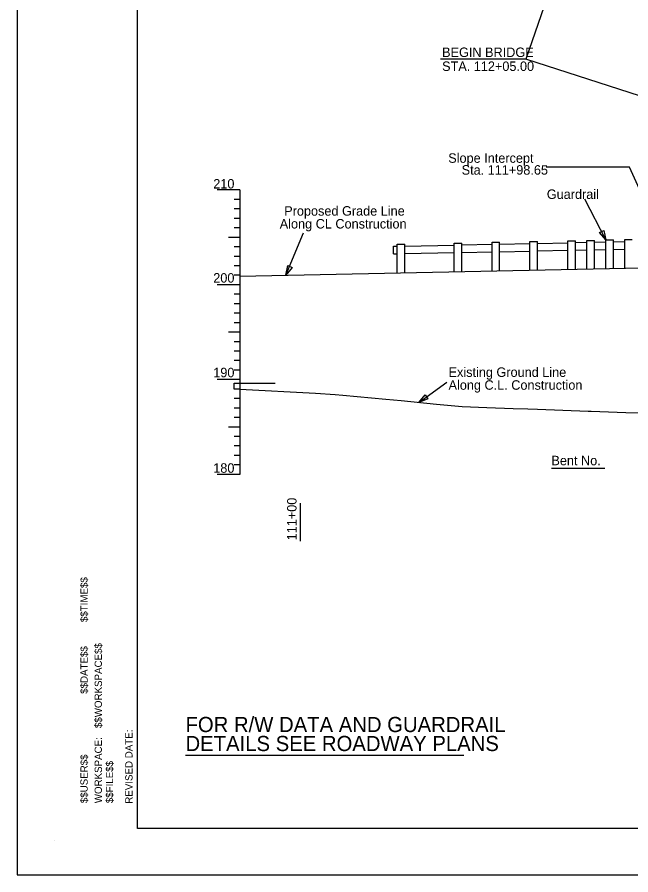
# Model space of a CAD drawing. Extents: x 1385284 to 1385995, y 1975154 to 1975620.
# Drawn here: x 1385283.8 to 1385445.7, y 1975153.7 to 1975379.9 of the extents above; entities that cross this region are included whole.
import ezdxf

# ---------------------------------------------------------------- set-up
doc = ezdxf.new("R2010")
doc.units = 0
for name, color, linetype in [('1', 7, 'Continuous'), ('Default', 7, 'Continuous'), ('Level 1', 7, 'Continuous'), ('R_Axis_Annotation', 7, 'Continuous'), ('R_Exist Surface', 7, 'Continuous'), ('R_Grid Annot', 7, 'Continuous'), ('R_Vert Alg', 7, 'Continuous')]:
    doc.layers.add(name, color=color, linetype=linetype)

msp = doc.modelspace()

# ---------------------------------------------------------------- linework, layer by layer
at = {"layer": '1'}
msp.add_line((1385293.63, 1975162.8), (1385293.63, 1975162.8), dxfattribs=at)
for points in [[(1385994.75, 1975619.62), (1385283.84, 1975619.62), (1385283.84, 1975153.74), (1385994.75, 1975153.74)], [(1385315.54, 1975165.95), (1385315.54, 1975607.41), (1385810.69, 1975607.41), (1385810.69, 1975586.48), (1385892.57, 1975586.48), (1385892.57, 1975580.3), (1385982.69, 1975580.3), (1385982.69, 1975165.95)]]:
    msp.add_lwpolyline(points, close=True, dxfattribs=at)
at = {"layer": 'Default'}
for p, q in [((1385459.1, 1975487.36), (1385417.98, 1975368.8)), ((1385417.98, 1975368.8), (1385395.52, 1975368.8)), ((1385459.1, 1975355.48), (1385417.98, 1975368.8)), ((1385445.3, 1975340.33), (1385423.35, 1975340.33)), ((1385457.22, 1975313.97), (1385445.3, 1975340.33)), ((1385342.56, 1975334.31), (1385342.56, 1975259.31)), ((1385342.56, 1975331.81), (1385341.06, 1975331.81)), ((1385439.08, 1975321.13), (1385433.59, 1975331.88)), ((1385342.56, 1975329.31), (1385341.06, 1975329.31)), ((1385342.56, 1975326.81), (1385341.06, 1975326.81)), ((1385342.56, 1975324.31), (1385341.06, 1975324.31)), ((1385342.56, 1975321.81), (1385339.56, 1975321.81)), ((1385354.71, 1975311.88), (1385359.35, 1975323.02)), ((1385342.56, 1975319.31), (1385341.06, 1975319.31)), ((1385383.07, 1975319.46), (1385384.07, 1975319.48)), ((1385383.07, 1975317.46), (1385383.07, 1975319.46)), ((1385384.07, 1975312.48), (1385384.07, 1975320)), ((1385384.07, 1975320), (1385386.07, 1975320)), ((1385386.07, 1975312.52), (1385386.07, 1975320)), ((1385386.07, 1975319.52), (1385399.07, 1975319.79)), ((1385399.07, 1975312.79), (1385399.07, 1975320.31)), ((1385399.07, 1975320.31), (1385401.07, 1975320.31)), ((1385401.07, 1975312.83), (1385401.07, 1975320.31)), ((1385401.07, 1975319.83), (1385409.07, 1975319.99)), ((1385409.07, 1975312.99), (1385409.07, 1975320.52)), ((1385409.07, 1975320.52), (1385411.07, 1975320.52)), ((1385411.07, 1975313.03), (1385411.07, 1975320.52)), ((1385411.07, 1975320.04), (1385419.07, 1975320.2)), ((1385419.07, 1975313.2), (1385419.07, 1975320.72)), ((1385419.07, 1975320.72), (1385421.07, 1975320.72)), ((1385421.07, 1975313.24), (1385421.07, 1975320.72)), ((1385421.07, 1975320.24), (1385429.07, 1975320.41)), ((1385429.07, 1975313.4), (1385429.07, 1975320.93)), ((1385429.07, 1975320.93), (1385431.07, 1975320.93)), ((1385431.07, 1975313.44), (1385431.07, 1975320.93)), ((1385431.07, 1975320.45), (1385434.07, 1975320.51)), ((1385434.07, 1975313.51), (1385434.07, 1975321.03)), ((1385434.07, 1975321.03), (1385436.07, 1975321.03)), ((1385436.07, 1975313.55), (1385436.07, 1975321.03)), ((1385436.07, 1975320.55), (1385439.07, 1975320.61)), ((1385439.07, 1975313.61), (1385439.07, 1975321.13)), ((1385439.07, 1975321.13), (1385441.07, 1975321.13)), ((1385441.07, 1975313.65), (1385441.07, 1975321.13)), ((1385441.07, 1975320.65), (1385444.07, 1975320.71)), ((1385444.07, 1975313.71), (1385444.07, 1975321.23)), ((1385444.07, 1975321.23), (1385446.07, 1975321.23)), ((1385383.07, 1975317.46), (1385384.07, 1975317.48)), ((1385386.07, 1975317.52), (1385399.07, 1975317.79)), ((1385401.07, 1975317.83), (1385409.07, 1975317.99)), ((1385411.07, 1975318.04), (1385419.07, 1975318.2)), ((1385421.07, 1975318.24), (1385429.07, 1975318.4)), ((1385431.07, 1975318.45), (1385434.07, 1975318.51)), ((1385436.07, 1975318.55), (1385439.07, 1975318.61)), ((1385441.07, 1975318.65), (1385444.07, 1975318.71)), ((1385342.56, 1975316.81), (1385341.06, 1975316.81)), ((1385342.56, 1975314.31), (1385341.06, 1975314.31)), ((1385342.56, 1975311.81), (1385341.06, 1975311.81)), ((1385342.56, 1975306.81), (1385341.06, 1975306.81)), ((1385342.56, 1975304.31), (1385341.06, 1975304.31)), ((1385342.56, 1975301.81), (1385341.06, 1975301.81)), ((1385342.56, 1975299.31), (1385341.06, 1975299.31)), ((1385342.56, 1975296.81), (1385339.56, 1975296.81)), ((1385342.56, 1975294.31), (1385341.06, 1975294.31)), ((1385342.56, 1975291.81), (1385341.06, 1975291.81)), ((1385342.56, 1975289.31), (1385341.06, 1975289.31)), ((1385342.56, 1975286.81), (1385341.06, 1975286.81)), ((1385341.06, 1975281.81), (1385341.06, 1975283.41)), ((1385341.06, 1975283.41), (1385351.89, 1975283.41)), ((1385389.74, 1975278.32), (1385397.15, 1975283.65)), ((1385342.56, 1975281.81), (1385341.06, 1975281.81)), ((1385342.56, 1975279.31), (1385341.06, 1975279.31)), ((1385342.56, 1975276.81), (1385341.06, 1975276.81)), ((1385342.56, 1975274.31), (1385341.06, 1975274.31)), ((1385342.56, 1975271.81), (1385339.56, 1975271.81)), ((1385342.56, 1975269.31), (1385341.06, 1975269.31)), ((1385342.56, 1975266.81), (1385341.06, 1975266.81)), ((1385342.56, 1975264.31), (1385341.06, 1975264.31)), ((1385342.56, 1975261.81), (1385341.06, 1975261.81)), ((1385438.84, 1975260.9), (1385424.72, 1975260.9)), ((1385358.56, 1975241.72), (1385358.56, 1975251.72))]:
    msp.add_line(p, q, dxfattribs=at)
for points in [[(1385438.6, 1975323.66), (1385439.08, 1975321.13), (1385437.46, 1975323.14)], [(1385356.33, 1975313.88), (1385354.71, 1975311.88), (1385355.2, 1975314.41)], [(1385392.14, 1975279.28), (1385389.74, 1975278.32), (1385391.41, 1975280.29)]]:
    msp.add_lwpolyline(points, close=True, dxfattribs=at)
at = {"layer": 'Level 1'}
msp.add_line((1385328.2, 1975185.3), (1385401.66, 1975185.3), dxfattribs=at)
at = {"layer": 'R_Exist Surface'}
msp.add_lwpolyline([(1385342.56, 1975281.77), (1385362.55, 1975280.71), (1385367.71, 1975280.36), (1385369.76, 1975280.21), (1385381.05, 1975279.16), (1385385.08, 1975278.77), (1385394.4, 1975277.88), (1385401.16, 1975277.21), (1385407.74, 1975276.97), (1385414.63, 1975276.7), (1385418.52, 1975276.57), (1385421.08, 1975276.48), (1385434.43, 1975276.03), (1385435.24, 1975276), (1385444.39, 1975275.65), (1385447.77, 1975275.52)], dxfattribs=at)
at = {"layer": 'R_Grid Annot'}
for p, q in [((1385342.56, 1975334.31), (1385336.56, 1975334.31)), ((1385342.56, 1975309.31), (1385336.56, 1975309.31)), ((1385342.56, 1975284.31), (1385336.56, 1975284.31)), ((1385342.56, 1975259.31), (1385336.56, 1975259.31))]:
    msp.add_line(p, q, dxfattribs=at)
at = {"layer": 'R_Vert Alg'}
msp.add_line((1385342.56, 1975311.63), (1385448.5, 1975313.8), dxfattribs=at)

# ---------------------------------------------------------------- texts
at = {"layer": '1'}
for s, height, p in [('$$TIME$$', 1.919, (1385302.44, 1975220.38)), ('$$DATE$$', 1.919, (1385302.44, 1975201.47)), ('$$WORKSPACE$$', 1.9195, (1385306.19, 1975192.44)), ('REVISED DATE:', 1.9195, (1385314.27, 1975172.5)), ('WORKSPACE:', 1.919, (1385306.19, 1975172.63)), ('$$USER$$', 1.919, (1385302.44, 1975172.64)), ('$$FILE$$', 1.919, (1385309.15, 1975172.64))]:
    msp.add_text(s, height=height, rotation=90, dxfattribs=at).set_placement(p)
at = {"layer": 'Default'}
for s, p in [('BEGIN BRIDGE', (1385395.91, 1975369.37)), ('STA. 112+05.00', (1385395.91, 1975365.69)), ('Slope Intercept', (1385397.53, 1975341.48)), ('Sta. 111+98.65', (1385401.06, 1975338.35)), ('Guardrail', (1385423.52, 1975331.95)), ('Proposed Grade Line ', (1385354.27, 1975327.54)), ('Along CL Construction ', (1385353.09, 1975324.15)), ('Existing Ground Line', (1385397.61, 1975285.03)), ('Along C.L. Construction', (1385397.61, 1975281.64))]:
    msp.add_text(s, height=2.5, dxfattribs=at).set_placement(p)
at = {"layer": 'Level 1'}
for s, p in [('FOR R/W DATA AND GUARDRAIL', (1385328.24, 1975191.38)), ('DETAILS SEE ROADWAY PLANS', (1385328.24, 1975186.37))]:
    msp.add_text(s, height=4, dxfattribs=at).set_placement(p)
at = {"layer": 'R_Axis_Annotation'}
for s, p in [('210', (1385335.56, 1975334.7)), ('200', (1385335.56, 1975309.88)), ('190', (1385335.56, 1975284.93)), ('Bent No.', (1385424.74, 1975261.73)), ('180', (1385335.56, 1975259.75))]:
    msp.add_text(s, height=2.5, dxfattribs=at).set_placement(p)
msp.add_text('111+00', height=2.5, rotation=90, dxfattribs=at).set_placement((1385357.53, 1975241.93))

doc.saveas('drawing.dxf')
